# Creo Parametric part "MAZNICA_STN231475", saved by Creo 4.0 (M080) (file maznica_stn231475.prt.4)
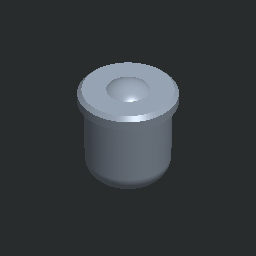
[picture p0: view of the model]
Units: millimeter Kilogram Sec (mmKs); MM, KILOGRAM, SECS
Materials in the file: OCEL_N

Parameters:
  MFG_WP_MATERIAL = "OCEL"
  NAZOV = "MAZNICA_STN231475"
  NORMA = "STN 23 1475"
  PTC_MATERIAL_NAME = "OCEL_N"

Other parameters: HMOTNOST, HUSTOTA, D5

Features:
  1. chamfer
  2. round

Layers: 1, 2, 3, 4, 5, 6, 7, 8, 9, 10, 11, 12, 13, 14, 15, 16, 17, 18, 19, 20, 21, 22, 23, 24, 25, 26, 27, 28, 29, 30, 31, 32

Family table entries: GENERIC, MAZNICA_6, MAZNICA_STN231475, value(d_val), value(i_val), MAZNICA_8, MAZNICA_STN231475, !/ , 2/", 2/!, MAZNICA_10, MAZNICA_STN231475, !/$, 2/&, 2/%, MAZNICA_12, MAZNICA_STN231475, !/(, 2/*, 2/), # Pro/TABLE, [] S 92;, [] W 10;, [A] W  3;, [B] W 11;, [C] W 10;, [D] W 10;, [E] W 10;, [F] W 10;, [G] W 10;

Surfaces: 6 cone, 4 torus, 3 plane, 2 cylinder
